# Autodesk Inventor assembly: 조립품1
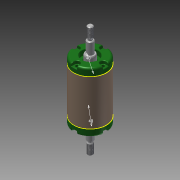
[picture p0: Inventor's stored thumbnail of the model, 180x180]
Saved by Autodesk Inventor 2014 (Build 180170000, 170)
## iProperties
Created: 2015-11
Part Number: 조립품1
Document SubType Name: Assembly
Designer: 3sil_66666
Author: 3sil_66666
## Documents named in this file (4)
- C:\Users\3sil_66666\Desktop\451110V1045\조립품1.iam
- C:\Users\3sil_66666\Desktop\451110V1045\본체.ipt
- C:\Users\3sil_66666\Desktop\451110V1045\커버.ipt
- C:\Users\3sil_66666\Desktop\451110V1045\축.ipt
